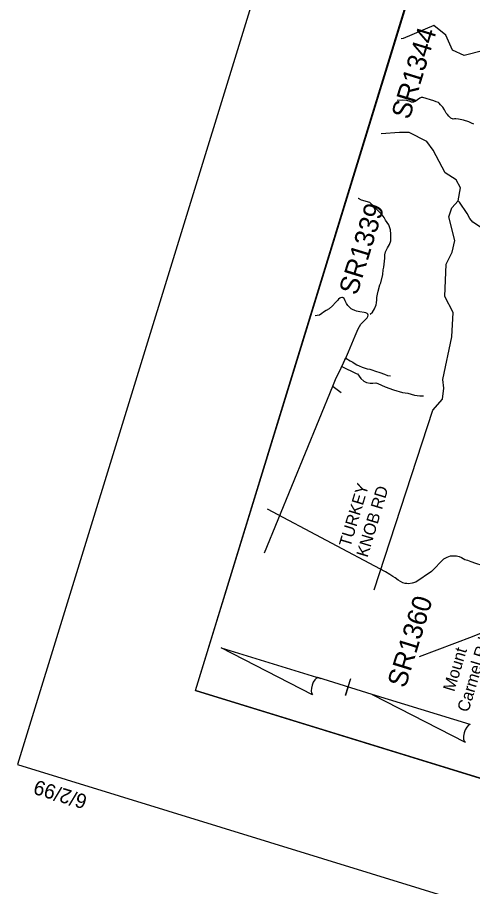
# Model space of a CAD drawing. Extents: x 1348011 to 1349268, y 1028333 to 1030014.
# Drawn here: x 1348011.3 to 1348154.1, y 1028708.2 to 1028980.8 of the extents above; entities that cross this region are included whole.
import ezdxf

# ---------------------------------------------------------------- set-up
doc = ezdxf.new("R2010")
doc.units = 0
for name, color, linetype in [('CTL Sheet Border CELL', 7, 'Continuous'), ('Prop Leader Line Light', 7, 'Continuous'), ('Prop Leader Line Medium', 7, 'Continuous'), ('Prop North Arrow for Plan Sheets CELL', 7, 'Continuous'), ('Prop WCC CELL', 7, 'Continuous'), ('Scratch_Level_3', 7, 'Continuous')]:
    doc.layers.add(name, color=color, linetype=linetype)

msp = doc.modelspace()

# ---------------------------------------------------------------- linework, layer by layer
at = {"layer": 'CTL Sheet Border CELL'}
msp.add_lwpolyline([(1348395.15, 1029993.01), (1348011.26, 1028746.43), (1348883.85, 1028477.71), (1349267.74, 1029724.29)], close=True, dxfattribs=at)
at = {"layer": 'Prop Leader Line Medium'}
for points in [[(1348157.6, 1028970.38), (1348151.43, 1028968.83), (1348147.75, 1028970.54), (1348145.7, 1028975.22), (1348141.96, 1028978.25), (1348132.31, 1028974.2), (1348131.71, 1028974.01)], [(1348154.5, 1028947.26), (1348153.77, 1028947.65), (1348152.93, 1028948.07), (1348151.25, 1028948.51), (1348149.69, 1028948.81), (1348148.89, 1028949.01), (1348148.39, 1028949), (1348147.99, 1028948.89), (1348147.25, 1028949.2), (1348146.69, 1028949.79), (1348146.23, 1028950.32), (1348145.85, 1028950.77), (1348145.33, 1028951.74), (1348144.75, 1028952.58), (1348144.08, 1028953.39), (1348143.62, 1028953.92), (1348143.43, 1028954.04), (1348142.72, 1028954.26), (1348141.89, 1028954.56), (1348138.49, 1028955.65), (1348137.97, 1028955.64), (1348137.52, 1028955.42), (1348136.83, 1028954.9), (1348136.04, 1028954.36), (1348135.59, 1028954.15), (1348134.98, 1028954.22), (1348134.48, 1028954.4), (1348133.47, 1028954.67), (1348132.1, 1028954.8), (1348130.43, 1028954.69)], [(1348123.17, 1028801.19), (1348141.65, 1028857.57), (1348144.65, 1028861.04), (1348145.1, 1028864.54), (1348144.81, 1028867.24), (1348147.56, 1028880.6), (1348147.99, 1028888.27), (1348145.44, 1028893.28), (1348145.79, 1028903.42), (1348147.67, 1028907.13), (1348148.53, 1028910.84), (1348146.62, 1028918.25), (1348147.54, 1028921.07), (1348149.53, 1028923.24), (1348150.31, 1028927.29), (1348149, 1028929.8), (1348145.53, 1028931.98), (1348141.76, 1028939.1), (1348139.71, 1028941.87), (1348134.2, 1028944.69), (1348131.12, 1028944.67), (1348125.44, 1028944.23)], [(1348121.99, 1028887.74), (1348122.73, 1028888.38), (1348123.34, 1028889.42), (1348123.87, 1028890.6), (1348123.99, 1028891.3), (1348124.07, 1028892.19), (1348124.01, 1028892.98), (1348124.22, 1028893.94), (1348124.46, 1028894.9), (1348124.95, 1028896.91), (1348125.34, 1028897.55), (1348125.9, 1028900.1), (1348126.06, 1028901.61), (1348126.22, 1028902.48), (1348126.52, 1028905.27), (1348126.54, 1028906.3), (1348126.79, 1028907.3), (1348127.45, 1028908.46), (1348128.07, 1028909.57), (1348128.47, 1028910.73), (1348128.46, 1028911.61), (1348128.44, 1028912.77), (1348128.34, 1028914.13), (1348127.77, 1028915.74), (1348126.77, 1028917.21), (1348126.32, 1028918.06), (1348125.7, 1028918.84), (1348124.31, 1028920.29), (1348123.2, 1028921.51), (1348121.81, 1028922.76), (1348119.27, 1028923.46), (1348118.26, 1028923.97), (1348118.23, 1028923.99)], [(1348174.23, 1028901.81), (1348172.43, 1028904.35), (1348171.49, 1028905.82), (1348169.91, 1028908.88), (1348167.46, 1028911.35), (1348163.61, 1028913.23), (1348161.5, 1028913.92), (1348158.7, 1028915.16), (1348156.57, 1028915.02), (1348154.23, 1028916.54), (1348153.26, 1028917.68), (1348152.4, 1028919.26), (1348150.03, 1028922.86), (1348149.53, 1028923.24)], [(1348088.8, 1028812.87), (1348110.22, 1028865.13), (1348110.68, 1028866.19), (1348111.11, 1028867.18), (1348112.88, 1028870.89), (1348114.57, 1028874.47), (1348115.17, 1028875.88), (1348117.22, 1028880.89), (1348118.22, 1028883.13), (1348119.05, 1028884.58), (1348119.63, 1028885.22), (1348120.6, 1028886.16), (1348120.97, 1028886.6), (1348121.25, 1028886.96), (1348121.3, 1028887.37), (1348121.2, 1028887.67), (1348121.02, 1028887.91), (1348120.62, 1028888.14), (1348120.11, 1028888.27), (1348118.76, 1028888.46), (1348117.67, 1028888.69), (1348117.15, 1028888.81), (1348116.42, 1028889.13), (1348116.04, 1028889.38), (1348115.45, 1028889.92), (1348114.99, 1028890.42), (1348114.57, 1028891.07), (1348114.16, 1028891.9), (1348113.75, 1028892.64), (1348113.49, 1028892.87), (1348113.27, 1028892.94), (1348113.02, 1028892.95), (1348112.7, 1028892.87), (1348112.44, 1028892.69), (1348112.06, 1028892.4), (1348111.73, 1028892.03), (1348111.13, 1028891.36), (1348110.19, 1028890.28), (1348109.05, 1028889.41), (1348108.11, 1028888.84), (1348107.33, 1028888.28), (1348106.81, 1028887.94), (1348106.02, 1028887.43), (1348105.28, 1028887.24), (1348104.72, 1028887.23)], [(1348113.08, 1028871.25), (1348114.01, 1028873.34), (1348114.31, 1028873.85)], [(1348114.31, 1028873.85), (1348115.73, 1028873.06), (1348116.54, 1028872.6), (1348117.29, 1028872.16), (1348117.73, 1028871.81), (1348118.51, 1028871.46), (1348119.44, 1028871.08), (1348120.13, 1028870.92), (1348120.99, 1028870.59), (1348121.84, 1028870.4), (1348122.44, 1028870.27), (1348123.61, 1028869.87), (1348124.97, 1028869.41), (1348126.5, 1028868.86), (1348127.41, 1028868.49), (1348128.34, 1028868.34)], [(1348113.08, 1028871.25), (1348117.52, 1028869.14), (1348118.03, 1028868.95), (1348118.5, 1028868.29), (1348119.01, 1028867.56), (1348120.01, 1028866.71), (1348120.84, 1028866.24), (1348121.92, 1028866.04), (1348122.82, 1028866.06), (1348123.78, 1028866.2), (1348124.32, 1028865.95), (1348126.69, 1028864.93), (1348129.26, 1028863.96), (1348132.13, 1028863.14), (1348133.77, 1028862.88), (1348135.87, 1028862.29), (1348137.58, 1028862.04), (1348138.7, 1028862.06)], [(1348110.3, 1028865.03), (1348112.83, 1028863.11)], [(1348141.2, 1028806.99), (1348136.3, 1028803.64), (1348135.19, 1028803.29), (1348134.04, 1028803.11), (1348133.48, 1028803.22), (1348132.9, 1028803.27), (1348132.21, 1028803.45), (1348131.44, 1028803.81), (1348130.79, 1028804.26), (1348129.85, 1028805.04), (1348129.11, 1028805.42), (1348128.17, 1028806.03), (1348126.79, 1028806.88), (1348089.78, 1028826.56)], [(1348141.2, 1028806.99), (1348145.08, 1028810.92), (1348146.1, 1028811.48), (1348147.19, 1028811.88), (1348147.76, 1028811.88), (1348148.35, 1028811.94), (1348149.05, 1028811.9), (1348149.88, 1028811.7), (1348150.6, 1028811.38), (1348151.67, 1028810.8), (1348152.47, 1028810.57), (1348153.52, 1028810.15), (1348155.03, 1028809.58), (1348157.03, 1028808.97)], [(1348177.2, 1028791.24), (1348172.17, 1028791.25), (1348170.95, 1028791.36), (1348170.13, 1028791.25), (1348169, 1028791.22), (1348167.38, 1028791.14), (1348165.3, 1028790.89), (1348163.83, 1028790.58), (1348162.62, 1028790.18), (1348161.54, 1028789.7), (1348159.82, 1028789), (1348158.27, 1028788.34), (1348156.31, 1028787.43), (1348154.01, 1028786.51), (1348137.34, 1028780.26)]]:
    msp.add_lwpolyline(points, dxfattribs=at)
at = {"layer": 'Prop North Arrow for Plan Sheets CELL'}
for p, q in [((1348075.22, 1028783.04), (1348075.21, 1028783.01)), ((1348075.22, 1028783.04), (1348075.21, 1028783.01)), ((1348103.84, 1028768.33), (1348075.21, 1028783.01)), ((1348075.22, 1028783.04), (1348106.44, 1028773.43)), ((1348122.64, 1028768.44), (1348105.53, 1028773.71)), ((1348106.44, 1028773.43), (1348105.56, 1028773.7)), ((1348114.27, 1028768.19), (1348115.88, 1028773.42)), ((1348114.97, 1028770.48), (1348114.26, 1028768.16)), ((1348114.26, 1028768.16), (1348114.25, 1028768.13)), ((1348122.64, 1028768.44), (1348151.82, 1028753.48)), ((1348153.38, 1028759.01), (1348122.64, 1028768.44))]:
    msp.add_line(p, q, dxfattribs=at)
for centre, start_param, end_param in [((1348104.99, 1028770.93), 0.216388, 2.908219), ((1348152.78, 1028756.22), 0.201328, 3.141593)]:
    msp.add_ellipse(centre, major_axis=(0.87, 2.76), ratio=0.461098, start_param=start_param, end_param=end_param, dxfattribs=at)
at = {"layer": 'Prop WCC CELL'}
msp.add_lwpolyline([(1348067.18, 1028769.65), (1348163, 1029082), (1348341.6, 1029027), (1348245.78, 1028714.65)], close=True, dxfattribs=at)
at = {"layer": 'Scratch_Level_3'}
for q in [(1348187.56, 1029160.56), (1348711.01, 1028571.38)]:
    msp.add_line((1348067.18, 1028769.65), q, dxfattribs=at)

# ---------------------------------------------------------------- texts
at = {"layer": 'CTL Sheet Border CELL'}
msp.add_text('6/2/99', height=4.565, rotation=162.8834, dxfattribs=at).set_placement((1348033.51, 1028736.73))
at = {"layer": 'Prop Leader Line Light'}
for s, p in [('SR1344', (1348134.26, 1028948.48)), ('SR1339', (1348117.82, 1028893.36)), ('SR1360', (1348133.02, 1028770.2))]:
    msp.add_text(s, height=6.055, rotation=72.8834, dxfattribs=at).set_placement(p)
at = {"layer": 'Prop Leader Line Medium'}
for s, p in [('TURKEY', (1348115.69, 1028814.4)), ('KNOB RD', (1348121.11, 1028811.2)), ('Carmel Rd', (1348152.77, 1028762.64)), ('Mount ', (1348148.33, 1028769.09))]:
    msp.add_text(s, height=3.763, rotation=73.1908, dxfattribs=at).set_placement(p)

doc.saveas('drawing.dxf')
